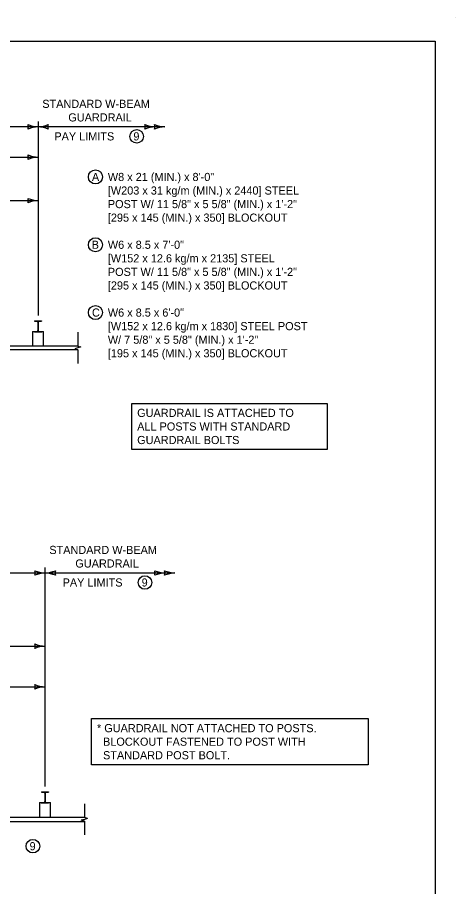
# Model space of a CAD drawing. Extents: x 49991.4 to 50021, y 49987.6 to 50011.4.
# Drawn here: x 50013.67 to 50016.9, y 49992.77 to 49999.18 of the extents above; entities that cross this region are included whole.
import ezdxf

# ---------------------------------------------------------------- set-up
doc = ezdxf.new("R2010")
doc.units = 0
for name, color, linetype in [('Level 1', 7, 'Continuous'), ('Level 2', 7, 'Continuous'), ('Level 3', 7, 'Continuous'), ('Level 6', 7, 'Continuous')]:
    doc.layers.add(name, color=color, linetype=linetype)

msp = doc.modelspace()

# ---------------------------------------------------------------- linework, layer by layer
at = {"layer": 'Level 1'}
for p, q in [((50016.9001, 49999.1756), (50016.9001, 49999.1756)), ((50013.7966, 49996.9372), (50013.8492, 49996.9372)), ((50013.7966, 49996.9372), (50013.7966, 49996.9344)), ((50013.7966, 49996.9344), (50013.8146, 49996.9344)), ((50013.8218, 49996.9272), (50013.8218, 49996.8672)), ((50013.824, 49996.9272), (50013.824, 49996.8672)), ((50013.8312, 49996.9344), (50013.8492, 49996.9344)), ((50013.8492, 49996.9372), (50013.8492, 49996.9344)), ((50013.7829, 49996.8601), (50013.7829, 49996.7533)), ((50013.7829, 49996.8601), (50013.7959, 49996.8601)), ((50013.7959, 49996.8572), (50013.7959, 49996.8601)), ((50013.7959, 49996.8572), (50013.8498, 49996.8572)), ((50013.7966, 49996.8572), (50013.7966, 49996.8601)), ((50013.7966, 49996.8601), (50013.8146, 49996.8601)), ((50013.8312, 49996.8601), (50013.8492, 49996.8601)), ((50013.8492, 49996.8572), (50013.8492, 49996.8601)), ((50013.8498, 49996.8572), (50013.8498, 49996.8601)), ((50013.8498, 49996.8601), (50013.8629, 49996.8601)), ((50013.8629, 49996.7533), (50013.8629, 49996.8601)), ((50014.1169, 49996.7242), (50009.6294, 49996.7242)), ((50009.7324, 49996.7533), (50013.9038, 49996.7533)), ((50013.9038, 49996.7533), (50014.1169, 49996.7533)), ((50013.9038, 49996.7533), (50014.1169, 49996.7533)), ((50014.1169, 49996.7533), (50014.1169, 49996.7533)), ((50013.8471, 49993.4645), (50013.8996, 49993.4645)), ((50013.8471, 49993.4645), (50013.8471, 49993.4616)), ((50013.8471, 49993.4616), (50013.8651, 49993.4616)), ((50013.8722, 49993.4545), (50013.8722, 49993.3944)), ((50013.8745, 49993.4545), (50013.8745, 49993.3944)), ((50013.8816, 49993.4616), (50013.8996, 49993.4616)), ((50013.8996, 49993.4645), (50013.8996, 49993.4616)), ((50013.8333, 49993.3873), (50013.8333, 49993.277)), ((50013.8333, 49993.3873), (50013.8464, 49993.3873)), ((50013.8464, 49993.3844), (50013.8464, 49993.3873)), ((50013.8464, 49993.3844), (50013.9003, 49993.3844)), ((50013.8471, 49993.3844), (50013.8471, 49993.3873)), ((50013.8471, 49993.3873), (50013.8651, 49993.3873)), ((50013.8816, 49993.3873), (50013.8996, 49993.3873)), ((50013.8996, 49993.3844), (50013.8996, 49993.3873)), ((50013.9003, 49993.3844), (50013.9003, 49993.3873)), ((50013.9003, 49993.3873), (50013.9134, 49993.3873)), ((50013.9134, 49993.277), (50013.9134, 49993.3873)), ((50009.1482, 49993.277), (50014.1642, 49993.277)), ((50009.1482, 49993.247), (50014.1642, 49993.247))]:
    msp.add_line(p, q, dxfattribs=at)
msp.add_lwpolyline([(49999.3835, 49998.9992), (50016.7501, 49998.9992), (50016.7501, 49987.7988), (49999.3835, 49987.7988)], close=True, dxfattribs=at)
for centre, start, end in [((50013.8146, 49996.9272), 0, 90), ((50013.8312, 49996.9272), 90, 180), ((50013.8146, 49996.8672), 270, 0), ((50013.8312, 49996.8672), 180, 270), ((50013.8651, 49993.4545), 0, 90), ((50013.8816, 49993.4545), 90, 180), ((50013.8651, 49993.3944), 270, 0), ((50013.8816, 49993.3944), 180, 270)]:
    msp.add_arc(centre, 0.00714, start, end, dxfattribs=at)
at = {"layer": 'Level 2'}
for p, q in [((50014.5132, 49995.9892), (50014.5132, 49996.3292)), ((50014.5132, 49996.3292), (50015.9528, 49996.3292)), ((50015.9528, 49996.3292), (50015.9528, 49995.9892)), ((50015.9528, 49995.9892), (50014.5132, 49995.9892)), ((50014.217, 49993.6648), (50014.217, 49994.0048)), ((50014.217, 49994.0048), (50016.2565, 49994.0048)), ((50016.2565, 49994.0048), (50016.2565, 49993.6648)), ((50016.2565, 49993.6648), (50014.217, 49993.6648))]:
    msp.add_line(p, q, dxfattribs=at)
for centre, radius in [((50014.5496, 49998.2982), 0.05), ((50014.2454, 49997.999), 0.0517), ((50014.2454, 49997.499), 0.0517), ((50014.2454, 49996.999), 0.0517), ((50014.6106, 49995.0088), 0.05), ((50013.7847, 49993.0641), 0.05)]:
    msp.add_circle(centre, radius, dxfattribs=at)
at = {"layer": 'Level 3'}
for p, q in [((50013.8229, 49998.4082), (50013.8229, 49997.8247)), ((50014.756, 49998.3682), (50009.8208, 49998.3682)), ((50009.8208, 49998.1447), (50013.8229, 49998.1447)), ((50013.8229, 49997.8635), (50013.8229, 49997.8247)), ((50013.8229, 49997.8635), (50013.8229, 49996.9772)), ((50009.8208, 49997.8247), (50013.8229, 49997.8247)), ((50013.8745, 49993.5045), (50013.8745, 49995.1188)), ((50009.7689, 49995.0788), (50014.8318, 49995.0788)), ((50010.0257, 49994.5391), (50013.8745, 49994.5391)), ((50009.7689, 49994.2391), (50013.8745, 49994.2391))]:
    msp.add_line(p, q, dxfattribs=at)
for centre, radius, start, end in [((50013.8318, 49998.5847), 0.2167, 247.45601, 267.63952), ((50013.6979, 49998.3682), 0.0534, 342.13882, 17.86118), ((50013.8117, 49998.595), 0.2271, 272.82731, 292.07716), ((50013.9478, 49998.3682), 0.0534, 162.13882, 197.86118), ((50014.6933, 49998.5847), 0.2167, 247.45601, 267.63952), ((50014.5594, 49998.3682), 0.0534, 342.13882, 17.86118), ((50014.7649, 49998.5847), 0.2167, 247.45601, 267.63952), ((50014.631, 49998.3682), 0.0534, 342.13882, 17.86118), ((50013.8341, 49998.1413), 0.2271, 92.82731, 112.07716), ((50013.8139, 49998.1517), 0.2167, 67.45601, 87.63952), ((50014.6956, 49998.1413), 0.2271, 92.82731, 112.07716), ((50014.7672, 49998.1413), 0.2271, 92.82731, 112.07716), ((50013.8318, 49998.3613), 0.2167, 247.45601, 267.63952), ((50013.6979, 49998.1447), 0.0534, 342.13882, 17.86118), ((50013.8341, 49997.9179), 0.2271, 92.82731, 112.07716), ((50013.8318, 49998.0413), 0.2167, 247.45601, 267.63952), ((50013.6979, 49997.8247), 0.0534, 342.13882, 17.86118), ((50013.8341, 49997.5979), 0.2271, 92.82731, 112.07716), ((50013.8837, 49995.3009), 0.2223, 247.45601, 267.63952), ((50013.7463, 49995.0788), 0.0548, 342.13882, 17.86118), ((50013.886, 49994.8461), 0.233, 92.82731, 112.07716), ((50013.863, 49995.3115), 0.233, 272.82731, 292.07716), ((50013.8654, 49994.8566), 0.2223, 67.45601, 87.63952), ((50014.0027, 49995.0788), 0.0548, 162.13882, 197.86118), ((50014.7675, 49995.3009), 0.2223, 247.45601, 267.63952), ((50014.6302, 49995.0788), 0.0548, 342.13882, 17.86118), ((50014.7699, 49994.8461), 0.233, 92.82731, 112.07716), ((50014.841, 49995.3009), 0.2223, 247.45601, 267.63952), ((50014.7036, 49995.0788), 0.0548, 342.13882, 17.86118), ((50014.8433, 49994.8461), 0.233, 92.82731, 112.07716), ((50013.8837, 49994.7612), 0.2223, 247.45601, 267.63952), ((50013.7463, 49994.5391), 0.0548, 342.13882, 17.86118), ((50013.886, 49994.3064), 0.233, 92.82731, 112.07716), ((50013.8837, 49994.4612), 0.2223, 247.45601, 267.63952), ((50013.7463, 49994.2391), 0.0548, 342.13882, 17.86118), ((50013.886, 49994.0064), 0.233, 92.82731, 112.07716)]:
    msp.add_arc(centre, radius, start, end, dxfattribs=at)
at = {"layer": 'Level 6'}
for p, q in [((50014.1169, 49996.8533), (50014.1169, 49996.7518)), ((50014.1391, 49996.7468), (50014.0947, 49996.731)), ((50014.0947, 49996.731), (50014.1169, 49996.7247)), ((50014.1169, 49996.7518), (50014.1391, 49996.7468)), ((50014.1169, 49996.7247), (50014.1169, 49996.6241)), ((50014.1642, 49993.377), (50014.1642, 49993.2756)), ((50014.1642, 49993.2618), (50014.1414, 49993.2549)), ((50014.1642, 49993.248), (50014.1414, 49993.2549)), ((50014.187, 49993.2687), (50014.1642, 49993.2756)), ((50014.187, 49993.2687), (50014.1642, 49993.2618)), ((50014.1642, 49993.248), (50014.1642, 49993.147))]:
    msp.add_line(p, q, dxfattribs=at)

# ---------------------------------------------------------------- texts
at = {"layer": 'Level 2'}
for s, p in [('STANDARD W-BEAM', (50013.8538, 49998.5082)), ('GUARDRAIL', (50014.0457, 49998.4082)), ('PAY LIMITS', (50013.9428, 49998.2682)), ('9', (50014.5251, 49998.2682)), ('A', (50014.2197, 49997.9689)), ('W8 x 21 (MIN.) x 8\'-0" ', (50014.3371, 49997.969)), ('[W203 x 31 kg/m (MIN.) x 2440] STEEL ', (50014.3371, 49997.869)), ('POST W/ 11 5/8" x 5 5/8" (MIN.) x 1\'-2" ', (50014.3371, 49997.769)), ('[295 x 145 (MIN.) x 350] BLOCKOUT', (50014.3371, 49997.669)), ('B', (50014.2177, 49997.469)), ('W6 x 8.5 x 7\'-0" ', (50014.3371, 49997.469)), ('[W152 x 12.6 kg/m x 2135] STEEL', (50014.3371, 49997.369)), ('POST W/ 11 5/8" x 5 5/8" (MIN.) x 1\'-2" ', (50014.3371, 49997.269)), ('[295 x 145 (MIN.) x 350] BLOCKOUT', (50014.3371, 49997.169)), ('C', (50014.2199, 49996.969)), ('W6 x 8.5 x 6\'-0" ', (50014.3371, 49996.969)), ('[W152 x 12.6 kg/m x 1830] STEEL POST ', (50014.3371, 49996.869)), ('W/ 7 5/8" x 5 5/8" (MIN.) x 1\'-2" ', (50014.3371, 49996.769)), ('[195 x 145 (MIN.) x 350] BLOCKOUT', (50014.3371, 49996.669)), ('GUARDRAIL IS ATTACHED TO', (50014.5532, 49996.2292)), ('ALL POSTS WITH STANDARD', (50014.5532, 49996.1292)), ('GUARDRAIL BOLTS', (50014.5532, 49996.0292)), ('STANDARD W-BEAM', (50013.9056, 49995.2188)), ('GUARDRAIL', (50014.0975, 49995.1188)), ('PAY LIMITS', (50014.0037, 49994.9788)), ('9', (50014.5861, 49994.9788)), ('* GUARDRAIL NOT ATTACHED TO POSTS.', (50014.257, 49993.9048)), ('  BLOCKOUT FASTENED TO POST WITH', (50014.257, 49993.8048)), ('  STANDARD POST BOLT.', (50014.257, 49993.7048)), ('9', (50013.7603, 49993.0341))]:
    msp.add_text(s, height=0.06, dxfattribs=at).set_placement(p)

doc.saveas('drawing.dxf')
